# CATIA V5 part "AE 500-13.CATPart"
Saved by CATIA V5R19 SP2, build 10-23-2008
Part number: AE 500-13
Bounding box of the stored display mesh (mm): x -22.494 to 22.494, y -22.494 to 22.494, z 0 to 75.4
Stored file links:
  C:\Users\Bora\Desktop\3D Katı model\AE serisi\AE 500\AE 500-13.CATPart
  C:\Program Files\Dassault Systemes\B19\intel_a\reffiles\standard\MetricThickPitch.txt
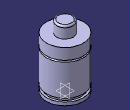
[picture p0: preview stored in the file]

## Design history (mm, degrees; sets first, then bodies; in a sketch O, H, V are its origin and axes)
Body1 (main body)
  Sketch1 on yz-plane, origin (0, 0, 0), H (0, 1, 0), V (0, 0, 1)
    point P1 (22.5, 45.9)
    point P8 (22.5, 47.9)
    point P9 (22.5, 47.9)
    point P10 (22.5, 45.9)
    point P11 (10, 73.4)
    point P13 (10, 73.4)
    line L1 (22.5, 45.9) -> (22.5, 8)
    line L2 (22.5, 4) -> (22.5, 0)
    line L3 (20, 8) -> (20, 4)
    line L4 (22.5, 61.4) -> (22.5, 47.9)
    arc A1 centre (22.5, 46.9) radius 1 from (22.5, 47.9) to (22.5, 45.9) ccw
    line L5 (10, 73.4) -> (10, 61.4)
    arc A2 centre (8, 73.4) radius 2 from (10, 73.4) to (8, 75.4) ccw
    line L6 (8, 75.4) -> (0, 75.4)
    line L7 (10, 61.4) -> (22.5, 61.4)
    line L8 (0, 0) -> (22.5, 0)
    line L9 (20, 8) -> (22.5, 8)
    line L10 (20, 4) -> (22.5, 4)
    tangency: L6 A2
    horizontal: L7 H, L8 H, L9 H, L10 H
    coincidence: P1 P10, P8 P9, P11 P13
  Shaft1: profile Sketch1, axis Sketch1.V, angle 360
  Sketch2 on face of Shaft1 from Sketch1.L8, origin (0, 0, 0), H (1, 0, 0), V (0, -1, 0)
    point P1 (10, 0)
    distance P1 V = 10
  Hole1: placed by Sketch2, at (10, 0, 0) direction (0, 0, 1), diameter 6.647, depth 13, threaded "M8", thread diameter 8, thread depth 13, pitch 1.25
  CircPattern1: of Hole1, instances 2, angular step 180, axis from xy-plane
